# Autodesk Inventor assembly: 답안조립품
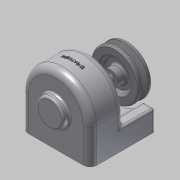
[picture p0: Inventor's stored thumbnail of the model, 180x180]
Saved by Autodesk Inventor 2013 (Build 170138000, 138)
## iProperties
Created: 2015-02
Part Number: 답안조립품
Document SubType Name: Assembly
Designer: Administrator
Author: Administrator
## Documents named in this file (14)
- C:\Users\Administrator\Desktop\450216V1002\답안조립품.iam
- C:\Users\Administrator\Desktop\450216V1002\본체.ipt
- C:\Users\Administrator\Desktop\450216V1002\축.ipt
- C:\Users\Administrator\Desktop\450216V1002\키4x4.ipt
- C:\Users\Administrator\Desktop\450216V1002\키5x5.ipt
- C:\Users\Administrator\Desktop\450216V1002\베어링 6001.ipt
- C:\Users\Administrator\Desktop\450216V1002\V-벨트풀리.ipt
- C:\Users\Administrator\Desktop\450216V1002\스퍼기어.ipt
- C:\Users\Administrator\Desktop\450216V1002\축커버.ipt
- C:\Users\Administrator\Desktop\450216V1002\M3x0.5.ipt
- C:\Users\Administrator\Desktop\450216V1002\오일실.ipt
- C:\Users\Administrator\Desktop\450216V1002\M5x0.8.ipt
- M5x0.8.ipt
- C:\Users\Administrator\Desktop\450216V1002\와샤.ipt
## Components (6 placed, 3 different names)
1. V-벨트풀리:1
2. M5x0.8:1 — 각도:1
3. M3x0.5:1
4. M3x0.5:2
5. M3x0.5:3
6. M3x0.5:4
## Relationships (1: Angle 1)
- 각도:1 [Angle]: M5x0.8:1
